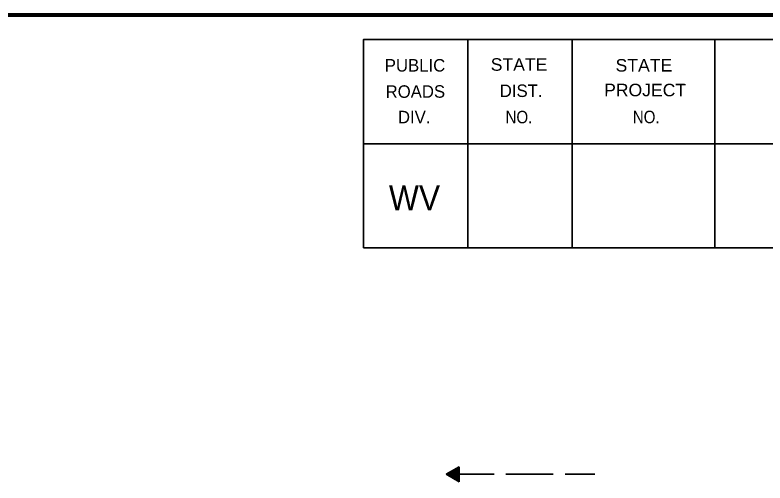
# Model space of a CAD drawing. Extents: x -90 to 623, y -379 to 75.
# Drawn here: x 465 to 541.1, y 21.9 to 69.4 of the extents above; entities that cross this region are included whole.
import ezdxf

# ---------------------------------------------------------------- set-up
doc = ezdxf.new("R2010")
doc.units = 0
doc.header["$LTSCALE"] = 0.8
doc.linetypes.add('LONG_DASHED', pattern=[7.5, 6, -1.5])
doc.layers.add('1', color=7, linetype='Continuous', lineweight=35)
doc.layers.add('61', color=7, linetype='Continuous', lineweight=35)

msp = doc.modelspace()

# ---------------------------------------------------------------- linework, layer by layer
at = {"layer": '1'}
for p, q in [((510.0782, 23.5257), (508.7701, 22.7703)), ((508.8773, 22.7282), (508.8773, 22.8346)), ((508.8971, 22.7171), (508.897, 22.8457)), ((508.9193, 22.7046), (508.9193, 22.8584)), ((508.9331, 22.6967), (508.933, 22.8662)), ((508.9617, 22.6807), (508.9617, 22.8824)), ((509.007, 22.6552), (509.007, 22.908)), ((509.0385, 22.6377), (509.0384, 22.9258)), ((509.0859, 22.6109), (509.086, 22.9527)), ((509.1313, 22.5855), (509.1312, 22.9785)), ((509.1602, 22.5693), (509.1602, 22.9948)), ((509.1863, 22.5546), (509.1863, 23.0096)), ((509.217, 22.5373), (509.2172, 23.027)), ((509.2454, 22.5214), (509.2455, 23.0432)), ((509.2792, 22.5024), (509.2792, 23.0622)), ((509.3098, 22.4852), (509.3098, 23.0796)), ((509.3374, 22.4697), (509.3374, 23.0953)), ((509.3787, 22.4465), (509.3787, 23.1186)), ((509.4001, 22.4346), (509.4002, 23.1308)), ((509.4384, 22.4131), (509.4384, 23.1523)), ((509.4737, 22.3933), (509.4734, 23.1723)), ((509.514, 22.3704), (509.514, 23.1952)), ((509.5522, 22.3491), (509.5523, 23.2169)), ((509.5797, 22.3337), (509.5796, 23.2324)), ((509.6067, 22.3185), (509.6067, 23.2478)), ((509.6334, 22.3036), (509.6334, 23.2628)), ((509.6502, 22.2942), (509.6502, 23.2724)), ((509.6725, 22.2816), (509.6724, 23.2852)), ((509.6959, 22.2684), (509.6961, 23.2982)), ((509.7237, 22.2528), (509.7237, 23.3141)), ((509.7543, 22.2355), (509.7544, 23.3313)), ((509.7788, 22.2218), (509.7788, 23.3452)), ((509.8032, 22.2081), (509.8032, 23.3591)), ((509.8117, 22.2035), (509.8117, 23.3638)), ((509.8484, 22.1827), (509.8486, 23.3848)), ((509.8714, 22.1698), (509.8714, 23.3977)), ((509.8852, 22.1621), (509.8853, 23.4055)), ((509.9074, 22.1497), (509.9074, 23.4181)), ((509.9426, 22.1299), (509.9426, 23.438)), ((509.9693, 22.1148), (509.9694, 23.4533)), ((510.0013, 22.0968), (510.0014, 23.4713)), ((510.0151, 22.0892), (510.0152, 23.4791)), ((510.0347, 22.0862), (510.0347, 23.4762)), ((510.0565, 22.0659), (510.0565, 23.5026)), ((510.0682, 22.0405), (510.0681, 23.5017)), ((510.0784, 22.015), (510.0782, 23.5257)), ((510.0784, 22.015), (508.7701, 22.7703)), ((508.8212, 22.7596), (508.8212, 22.8027)), ((508.8517, 22.7424), (508.8517, 22.8202))]:
    msp.add_line(p, q, dxfattribs=at)
at = {"layer": '1', "linetype": 'LONG_DASHED'}
msp.add_line((508.8232, 22.7838), (523.8232, 22.7838), dxfattribs=at)
at = {"layer": '1', "lineweight": 158}
msp.add_lwpolyline([(617.1938, 69.4188), (-42.5562, 69.3355), (-42.4728, -368.9978)], dxfattribs=at)
at = {"layer": '61'}
for p, q in [((510.9438, 66.9188), (510.9438, 45.7522)), ((521.5272, 66.9188), (521.5272, 45.7522)), ((536.0272, 66.9188), (536.0272, 45.7522)), ((614.6105, 56.3355), (500.3605, 56.3355))]:
    msp.add_line(p, q, dxfattribs=at)
for points in [[(614.6105, 66.9188), (500.3605, 66.9188), (500.3605, 45.7522)], [(614.6105, 66.9188), (614.6105, 45.7522), (500.3605, 45.7522)]]:
    msp.add_lwpolyline(points, dxfattribs=at)

# ---------------------------------------------------------------- texts
at = {"layer": '1', "width": 0.95}
msp.add_text('WV', height=2.54, dxfattribs=at).set_placement((502.9438, 49.5855))
at = {"layer": '61'}
for s, height, rotation, p in [('PUBLIC', 1.271, 0.033, (502.5272, 63.6688)), ('ROADS', 1.27, 0.124, (502.6105, 61.0022)), ('DIST.', 1.27, 0.056, (514.1938, 61.0855)), ('DIV.', 1.27, 359.932, (503.8605, 58.4188))]:
    msp.add_text(s, height=height, rotation=rotation, dxfattribs=at).set_placement(p)
for s, height, rotation, width, p in [('STATE', 1.271, 0.059, 1.05, (513.2772, 63.7522)), ('STATE', 1.271, 0.059, 1.05, (525.9438, 63.6688)), ('PROJECT', 1.27, 359.908, 1.05, (524.7772, 61.1688)), ('NO.', 1.27, 359.852, 0.9, (514.7772, 58.4188)), ('NO.', 1.271, 0.225, 0.9, (527.6938, 58.4188))]:
    msp.add_text(s, height=height, rotation=rotation, dxfattribs=dict(at, width=width)).set_placement(p)

doc.saveas('drawing.dxf')
